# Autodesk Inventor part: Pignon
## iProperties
Created: 2008-11
Part Number: Pignon
Document SubType Name: Modeling
Designer: ETUDIANT
Author: ETUDIANT
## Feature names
1. Extrusion1
2. Réseau circulaire1 [Circular Pattern]
3. Extrusion4
4. Extrusion5
5. Perçage1 [Hole]
